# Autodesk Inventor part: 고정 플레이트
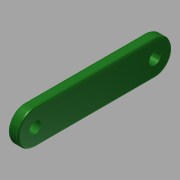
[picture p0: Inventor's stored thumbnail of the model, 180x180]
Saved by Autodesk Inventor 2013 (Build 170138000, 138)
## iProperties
Created: 2017-04
Part Number: 고정 플레이트
Material: 스테인리스강
Document SubType Name: Modeling
Designer: mduedu
Density: 8.08 g/cm^3
Mass: 9.86053 g
Surface Area: 11.4535 cm^2
Volume: 1.22036 cm^3
Author: mduedu
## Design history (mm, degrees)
sketch "스케치1"
  geometry: L1 (0, 17.5)-(0, -17.5); L2 (-5, 17.5)-(-5, -17.5); L3 (5, -17.5)-(5, 17.5); A1 r 5 centre (0, 17.5) between (5, 17.5) and (-5, 17.5); A2 r 5 centre (0, -17.5) between (-5, -17.5) and (5, -17.5); 2 further points
  constraints: 6 end point, 4 point on circle, 4 tangent, 3 coincident, 2 centre point, 1 midpoint, 1 parallel, 1 vertical
  dimensions: "d0" = 35 distance of L1.start L1.end; "d1" = 5 radius of A2
extrude "돌출1" new body sketch "스케치1" distance "d2" = 3; taper "d3" = 0 deg
fillet "모깎기1" dims "d4" = 0.5
sketch "스케치2"
  geometry: A1 r 5 centre (-17.5, 0) between (-17.5, 5) and (-17.5, -5) reference; A2 r 5 centre (17.5, 0) between (17.5, -5) and (17.5, 5) reference; 3 further points
  constraints: 2 coincident
sketch "스케치3"
  geometry: 3 further points
  constraints: 3 other
hole "구멍1" sketch "스케치3" at (-17.5, 0), (17.5, 0) diameter "d5" = 3.4; stored, may be unused: countersink angle "d9" = 90 deg, drill point angle "d11" = 0 deg; dims "d6" = 6, "d7" = 4, "d8" = 2, "d10" = 8
node "솔리드1"
